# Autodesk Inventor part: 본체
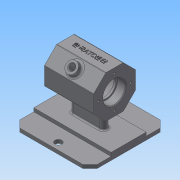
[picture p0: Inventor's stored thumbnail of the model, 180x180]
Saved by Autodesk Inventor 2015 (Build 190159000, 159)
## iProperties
Created: 2018-06
Part Number: 본체
Material: 일반
Document SubType Name: Modeling
Designer: ㅇㅅㅇ
Density: 1 g/cm^3
Appearance: 기본값
Mass: 204.339 g
Surface Area: 602.492 cm^2
Volume: 204.339 cm^3
Author: ㅇㅅㅇ
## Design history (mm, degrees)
sketch "스케치1"
  geometry: L1 (-55, -55)-(55, -55); L2 (55, -55)-(55, 55); L3 (55, 55)-(-55, 55); L4 (-55, 55)-(-55, -55); L5 (-55, -55)-(55, 55); L6 (55, -55)-(-55, 55); 1 further point
  constraints: 12 end point, 2 midpoint, 2 parallel, 1 horizontal, 1 perpendicular
  dimensions: "d0" = 110 distance between parallel lines of L1 L3; "d1" = 110 distance between parallel lines of L2 L4
extrude "돌출1" new body sketch "스케치1" distance "d2" = 5; taper "d3" = 0 deg
sketch "스케치2"
  geometry: L1 (-55, -55)-(-55, 55) reference; L2 (-55, 55)-(55, 55) reference; L3 (55, 55)-(55, -55) reference; L4 (55, -55)-(-55, -55) reference; L5 (-55, 25)-(55, 25); L6 (55, 25)-(55, -25); L7 (55, -25)-(-55, -25); L8 (-55, -25)-(-55, 25); 1 further point
  constraints: 8 end point, 2 parallel, 2 point on line, 1 horizontal, 1 perpendicular
  dimensions: "d5" = 30 distance between parallel lines of L5 L2; "d6" = 30 distance between parallel lines of L4 L7
extrude "돌출2" join sketch "스케치2" distance "d7" = 5; taper "d8" = 0 deg
sketch "스케치3"
  geometry: L1 (-55, 25)-(55, 25) reference; L2 (55, 55)-(55, 25) reference; L3 (-55, 55)-(55, 55) reference; L4 (-55, 25)-(-55, 55) reference; L5 (-55, -25)-(-55, 25) reference; L6 (55, -25)-(-55, -25) reference; L7 (55, -25)-(55, -55) reference; L8 (55, -55)-(-55, -55) reference; L9 (-55, -55)-(-55, -25) reference; L10 (55, 25)-(55, -25) reference; C1 r 5 at (0, 45); C2 r 5 at (0, -45); 1 further point
  constraints: 2 centre point
  dimensions: "d9" = 10 diameter of C1; "d10" = 10 diameter of C2; "d11" = 10 distance from line of C1.centre L3; "d12" = 55 distance from line of C1.centre L4; "d13" = 10 distance from line of L8 C2.centre; "d14" = 55 distance from line of L9 C2.centre
extrude "돌출3" cut sketch "스케치3" stored distance "d15" = 5; taper "d16" = 0 deg
sketch "스케치4"
  geometry: L1 (-55, 25)-(55, 25) reference; L2 (55, 25)-(55, -25) reference; L3 (55, -25)-(-55, -25) reference; L4 (-55, -25)-(-55, 25) reference; L5 (-19, 0)-(19, 0); L6 (-19, -5)-(19, -5); L7 (19, 5)-(-19, 5); L8 (55, 55)-(-55, 55) reference; A1 r 5 centre (-19, 0) between (-19, 5) and (-19, -5); A2 r 5 centre (19, 0) between (19, -5) and (19, 5); 2 further points
  constraints: 8 end point, 4 point on circle, 4 tangent, 2 centre point, 1 horizontal, 1 midpoint, 1 parallel
  dimensions: "d17" = 55 distance from line of point (0, 0) L4; "d18" = 38 distance of L5.start L5.end; "d19" = 5 radius of A1; "d20" = 55 distance between parallel lines of L5 L8
extrude "돌출4" join sketch "스케치4" distance "d21" = 52; taper "d22" = 0 deg
sketch "스케치5"
  geometry: L1 (50, 0)-(50, 5) reference; L2 (50, 5)-(55, 5) reference; L3 (55, 5)-(55, 0) reference; L4 (55, 0)-(50, 0) reference; L5 (25, 10)-(25, 5) reference; L6 (25, 5)-(40, 5) reference; L7 (40, 5)-(40, 0) reference; L8 (40, 0)-(-40, 0) reference; L9 (-40, 0)-(-40, 5) reference; L10 (-40, 5)-(-25, 5) reference; L11 (-25, 5)-(-25, 10) reference; L12 (-25, 10)-(-5, 10) reference; L13 (-5, 10)-(-5, 62) reference; L14 (-5, 62)-(5, 62) reference; L15 (5, 62)-(5, 10) reference; L16 (5, 10)-(25, 10) reference; L17 (-55, 0)-(-55, 5) reference; L18 (-55, 5)-(-50, 5) reference; L19 (-50, 5)-(-50, 0) reference; L20 (-50, 0)-(-55, 0) reference; L21 (12.426, 92)-(30, 74.426); L22 (30, 74.426)-(30, 49.574); L23 (30, 49.574)-(12.426, 32); L24 (12.426, 32)-(-12.426, 32); L25 (-12.426, 32)-(-30, 49.574); L26 (-30, 49.574)-(-30, 74.426); L27 (-30, 74.426)-(-12.426, 92); L28 (-12.426, 92)-(12.426, 92); C1 r 30 at (0, 62); 3 further points
  constraints: 16 end point, 2 midpoint, 1 centre point, 1 coincident, 1 tangent, 1 vertical alignment, 17 other
  dimensions: "d23" = 60 diameter of C1
extrude "돌출5" join sketch "스케치5" stored distance "d24" = 70; taper "d25" = 0 deg
sketch "스케치6"
  geometry: L1 (-24, 32)-(-35, 32) reference; L2 (-35, 32)-(-35, 92) reference; L3 (-35, 92)-(35, 92) reference; L4 (35, 92)-(35, 32) reference; L5 (35, 32)-(24, 32) reference; L6 (24, 32)-(24, 10) reference; L7 (24, 10)-(55, 10) reference; L8 (55, 10)-(55, 0) reference; L9 (55, 0)-(-55, 0) reference; L10 (-55, 0)-(-55, 10) reference; L11 (-55, 10)-(-24, 10) reference; L12 (-24, 10)-(-24, 32) reference; L13 (35, 74.426)-(35, 49.574) reference; L14 (35, 62)-(-35, 62); L15 (-35, 49.574)-(-35, 74.426) reference; L16 (35, 62)-(35, 78); L17 (35, 92)-(35, 74.426) reference; L18 (35, 78)-(23.3, 78); L19 (23, 77.7)-(23, 76); L20 (23, 76)-(20, 76); L21 (20, 76)-(20, 84); L22 (-35, 74.426)-(35, 74.426) reference; L23 (17, 87)-(-17, 87); L24 (-20, 84)-(-20, 76); L25 (-20, 76)-(-23, 76); L26 (-23, 76)-(-23, 77.7); L27 (-23.3, 78)-(-35, 78); L28 (-35, 78)-(-35, 62); A1 r 0.3 centre (23.3, 77.7) between (23.3, 78) and (23, 77.7); A2 r 0.3 centre (-23.3, 77.7) between (-23, 77.7) and (-23.3, 78); A3 r 3 centre (17, 84) between (20, 84) and (17, 87); A4 r 3 centre (-17, 84) between (-17, 87) and (-20, 84); 2 further points
  constraints: 24 end point, 8 point on circle, 8 point on line, 8 tangent, 6 perpendicular, 4 centre point, 2 equal radius, 2 midpoint, 1 collinear, 1 horizontal
  dimensions: "d26" = 32 diameter of L18 L14; "d27" = 28 diameter of L20 L14; "d28" = 50 diameter of L23 L14; "d29" = 12 distance between parallel lines of L19 L4; "d30" = 3 distance between parallel lines of L21 L19; "d31" = 12 distance between parallel lines of L28 L26; "d32" = 3 distance between parallel lines of L24 L26; "d33" = 0.3 radius of A1; "d34" = 3 radius of A3
revolve "회전1" sketch "스케치6" stored, may be unused: angle "d35" = 90 deg
sketch "스케치7" dims "d36" = 46
  geometry: L1 (49.574, 30)-(74.426, 30) reference; L2 (74.426, 30)-(92, 12.426) reference; L3 (92, 12.426)-(92, -12.426) reference; L4 (92, -12.426)-(74.426, -30) reference; L5 (74.426, -30)-(49.574, -30) reference; L6 (49.574, -30)-(32, -12.426) reference; L7 (32, -12.426)-(32, 12.426) reference; L8 (32, 12.426)-(49.574, 30) reference; L9 (5, -55)-(0, -55) reference; L10 (0, -55)-(0, 55) reference; L11 (0, 55)-(5, 55) reference; L12 (5, 55)-(5, 25) reference; L13 (5, 25)-(10, 25) reference; L14 (10, 25)-(10, -25) reference; L15 (10, -25)-(5, -25) reference; L16 (5, -25)-(5, -55) reference; L17 (62, 0)-(85, 0); C1 r 16 at (62, 0) reference; 2 further points
  constraints: 2 coincident, 2 end point, 1 horizontal, 1 horizontal alignment, 2 other
hole "구멍1" sketch "스케치7" at (85, 0) diameter "d37" = 3.242; stored, may be unused: countersink angle "d41" = 90 deg, drill point angle "d43" = 118 deg; dims "d38" = 8, "d39" = 4, "d40" = 2, "d42" = 10
chamfer "모따기1" distance "d47" = 10; stored, may be unused: second distance "d48" = 2, angle "d49" = 45 deg
sketch "스케치8"
  geometry: L1 (0, 0)-(0, 24.853) reference; L2 (0, 24.853)-(70, 24.853) reference; L3 (70, 24.853)-(70, 0) reference; L4 (70, 0)-(0, 0) reference; 2 further points
  constraints: 1 coincident, 1 other
feature "엠보싱1" sketch "스케치8" dims "d0" = 110, "d1" = 110, "d9" = 10, "d11" = 10, "d12" = 55, "d50" = 0.5, "d51" = 0
sketch "스케치9"
  geometry: L1 (0, 0)-(0, 24.853) reference; C1 r 8 at (35, 12.426); 2 further points
  constraints: 1 centre point, 1 horizontal alignment, 1 midpoint, 1 vertical alignment
  dimensions: "d52" = 16 diameter of C1
extrude "돌출6" join sketch "스케치9" distance "d53" = 7; taper "d54" = 0 deg
hole "구멍2" diameter "d57" = 8; stored, may be unused: countersink angle "d61" = 90 deg, drill point angle "d63" = 118 deg; dims "d55" = 10, "d56" = 10, "d58" = 8, "d59" = 4, "d60" = 2, "d62" = 18
chamfer "모따기2" distance "d64" = 1; stored, may be unused: second distance "d65" = 2, angle "d66" = 45 deg
fillet "모깎기1" dims "d67" = 1
fillet "모깎기2" dims "d68" = 2
chamfer "모따기3" distance "d69" = 1; stored, may be unused: second distance "d70" = 2, angle "d71" = 45 deg
fillet "모깎기3" dims "d72" = 3
node "솔리드1"
pattern_circular "원형 패턴1" dims angle "d45" = 360 deg
mirror "대칭1"
node "절단 모서리 투영1"
node "절단 모서리 투영2"
node "절단 모서리 투영3"
node "절단 모서리 투영4"
node "절단 모서리 투영5"
node "절단 모서리 투영6"
node "절단 모서리 투영7"
